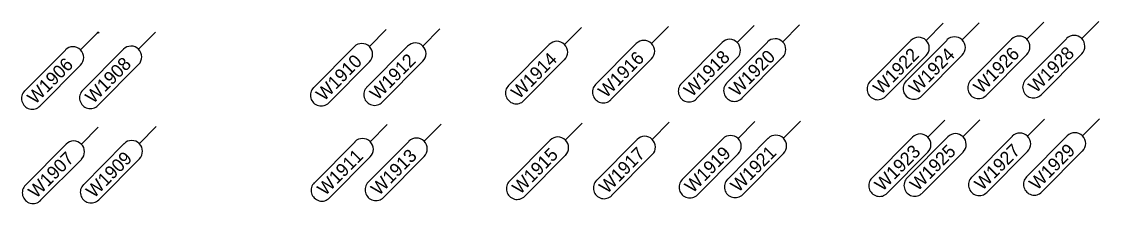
# Model space of a CAD drawing. Extents: x 12479652 to 12487250, y 9842710 to 9846560.
# Drawn here: x 12483341.6 to 12483444.7, y 9842833.3 to 9842850.7 of the extents above; entities that cross this region are included whole.
import ezdxf

# ---------------------------------------------------------------- set-up
doc = ezdxf.new("R2010")
doc.units = 0
doc.layers.add('_CIVIL_CONSTRUCTION', color=7, linetype='Continuous')
doc.layers.add('TextAlignmentLrg', color=7, linetype='Continuous')

msp = doc.modelspace()

# ---------------------------------------------------------------- linework, layer by layer
at = {"layer": '_CIVIL_CONSTRUCTION'}
for p, q in [((12483381.61, 9842849.99), (12483379.99, 9842848.36)), ((12483395.17, 9842850.14), (12483393.54, 9842848.51)), ((12483403.48, 9842850.23), (12483401.86, 9842848.6)), ((12483411.68, 9842850.33), (12483410.06, 9842848.69)), ((12483416.02, 9842850.37), (12483414.4, 9842848.74)), ((12483429.75, 9842850.53), (12483428.13, 9842848.9)), ((12483433.2, 9842850.57), (12483431.58, 9842848.94)), ((12483439.37, 9842850.64), (12483437.75, 9842849.01)), ((12483444.63, 9842850.7), (12483443.01, 9842849.07)), ((12483348.87, 9842849.62), (12483347.25, 9842847.99)), ((12483354.42, 9842849.68), (12483352.8, 9842848.05)), ((12483376.5, 9842849.93), (12483374.88, 9842848.3)), ((12483432.41, 9842845.09), (12483436.3, 9842849)), ((12483437.66, 9842845.15), (12483441.55, 9842849.06)), ((12483341.91, 9842844.07), (12483345.8, 9842847.98)), ((12483347.46, 9842844.13), (12483351.35, 9842848.05)), ((12483369.54, 9842844.38), (12483373.43, 9842848.29)), ((12483374.65, 9842844.44), (12483378.54, 9842848.35)), ((12483388.2, 9842844.59), (12483392.09, 9842848.5)), ((12483396.52, 9842844.69), (12483400.41, 9842848.6)), ((12483404.72, 9842844.78), (12483408.61, 9842848.69)), ((12483409.06, 9842844.83), (12483412.95, 9842848.74)), ((12483422.79, 9842844.98), (12483426.68, 9842848.89)), ((12483426.24, 9842845.02), (12483430.13, 9842848.93)), ((12483379.99, 9842846.91), (12483376.1, 9842842.99)), ((12483393.55, 9842847.06), (12483389.66, 9842843.15)), ((12483401.87, 9842847.15), (12483397.98, 9842843.24)), ((12483410.07, 9842847.24), (12483406.18, 9842843.33)), ((12483414.4, 9842847.29), (12483410.51, 9842843.38)), ((12483428.13, 9842847.45), (12483424.24, 9842843.53)), ((12483431.58, 9842847.49), (12483427.69, 9842843.57)), ((12483437.76, 9842847.56), (12483433.87, 9842843.64)), ((12483443.01, 9842847.61), (12483439.12, 9842843.7)), ((12483347.26, 9842846.54), (12483343.37, 9842842.62)), ((12483352.81, 9842846.6), (12483348.92, 9842842.69)), ((12483374.89, 9842846.85), (12483371, 9842842.93)), ((12483376.58, 9842840.85), (12483374.96, 9842839.21)), ((12483381.73, 9842840.89), (12483380.11, 9842839.26)), ((12483395.24, 9842841), (12483393.62, 9842839.37)), ((12483403.56, 9842841.07), (12483401.94, 9842839.44)), ((12483411.76, 9842841.14), (12483410.14, 9842839.51)), ((12483416.1, 9842841.17), (12483414.48, 9842839.54)), ((12483429.91, 9842841.29), (12483428.29, 9842839.66)), ((12483433.28, 9842841.32), (12483431.65, 9842839.68)), ((12483439.45, 9842841.37), (12483437.83, 9842839.74)), ((12483444.7, 9842841.41), (12483443.08, 9842839.78)), ((12483348.95, 9842840.62), (12483347.33, 9842838.98)), ((12483354.5, 9842840.66), (12483352.88, 9842839.03)), ((12483426.31, 9842835.77), (12483430.2, 9842839.68)), ((12483432.49, 9842835.82), (12483436.38, 9842839.73)), ((12483437.74, 9842835.86), (12483441.63, 9842839.78)), ((12483341.99, 9842835.07), (12483345.88, 9842838.98)), ((12483347.54, 9842835.11), (12483351.43, 9842839.03)), ((12483369.62, 9842835.3), (12483373.51, 9842839.21)), ((12483374.77, 9842835.34), (12483378.66, 9842839.25)), ((12483388.28, 9842835.45), (12483392.17, 9842839.36)), ((12483396.6, 9842835.52), (12483400.49, 9842839.43)), ((12483404.8, 9842835.59), (12483408.69, 9842839.5)), ((12483409.13, 9842835.62), (12483413.02, 9842839.54)), ((12483422.95, 9842835.74), (12483426.84, 9842839.65)), ((12483374.96, 9842837.76), (12483371.07, 9842833.85)), ((12483380.12, 9842837.81), (12483376.23, 9842833.89)), ((12483393.63, 9842837.92), (12483389.74, 9842834.01)), ((12483401.94, 9842837.99), (12483398.05, 9842834.07)), ((12483410.14, 9842838.06), (12483406.25, 9842834.14)), ((12483414.48, 9842838.09), (12483410.59, 9842834.18)), ((12483428.29, 9842838.21), (12483424.4, 9842834.29)), ((12483431.66, 9842838.23), (12483427.77, 9842834.32)), ((12483437.83, 9842838.29), (12483433.94, 9842834.37)), ((12483443.09, 9842838.33), (12483439.2, 9842834.42)), ((12483347.33, 9842837.53), (12483343.44, 9842833.62)), ((12483352.88, 9842837.58), (12483348.99, 9842833.67))]:
    msp.add_line(p, q, dxfattribs=at)
for centre, start, end in [((12483409.34, 9842847.97), 315.1702, 135.1702), ((12483413.68, 9842848.02), 315.1702, 135.1702), ((12483427.4, 9842848.17), 315.1702, 135.1702), ((12483430.85, 9842848.21), 315.1702, 135.1702), ((12483437.03, 9842848.28), 315.1702, 135.1702), ((12483442.28, 9842848.34), 315.1702, 135.1702), ((12483346.53, 9842847.26), 315.1702, 135.1702), ((12483352.08, 9842847.32), 315.1702, 135.1702), ((12483374.16, 9842847.57), 315.1702, 135.1702), ((12483379.27, 9842847.63), 315.1702, 135.1702), ((12483392.82, 9842847.78), 315.1702, 135.1702), ((12483401.14, 9842847.87), 315.1702, 135.1702), ((12483409.79, 9842844.1), 135.1702, 315.1702), ((12483423.51, 9842844.26), 135.1702, 315.1702), ((12483426.96, 9842844.3), 135.1702, 315.1702), ((12483433.14, 9842844.37), 135.1702, 315.1702), ((12483438.39, 9842844.43), 135.1702, 315.1702), ((12483342.64, 9842843.35), 135.1702, 315.1702), ((12483348.19, 9842843.41), 135.1702, 315.1702), ((12483370.27, 9842843.66), 135.1702, 315.1702), ((12483375.38, 9842843.72), 135.1702, 315.1702), ((12483388.93, 9842843.87), 135.1702, 315.1702), ((12483397.25, 9842843.96), 135.1702, 315.1702), ((12483405.45, 9842844.05), 135.1702, 315.1702), ((12483401.21, 9842838.71), 315.1702, 135.1702), ((12483409.42, 9842838.78), 315.1702, 135.1702), ((12483413.75, 9842838.81), 315.1702, 135.1702), ((12483427.56, 9842838.93), 315.1702, 135.1702), ((12483430.93, 9842838.96), 315.1702, 135.1702), ((12483437.1, 9842839.01), 315.1702, 135.1702), ((12483442.36, 9842839.05), 315.1702, 135.1702), ((12483346.6, 9842838.26), 315.1702, 135.1702), ((12483352.15, 9842838.3), 315.1702, 135.1702), ((12483374.23, 9842838.49), 315.1702, 135.1702), ((12483379.39, 9842838.53), 315.1702, 135.1702), ((12483392.9, 9842838.64), 315.1702, 135.1702), ((12483405.53, 9842834.87), 135.1702, 315.1702), ((12483409.86, 9842834.9), 135.1702, 315.1702), ((12483423.67, 9842835.02), 135.1702, 315.1702), ((12483427.04, 9842835.04), 135.1702, 315.1702), ((12483433.21, 9842835.1), 135.1702, 315.1702), ((12483438.47, 9842835.14), 135.1702, 315.1702), ((12483342.71, 9842834.34), 135.1702, 315.1702), ((12483348.26, 9842834.39), 135.1702, 315.1702), ((12483370.34, 9842834.57), 135.1702, 315.1702), ((12483375.5, 9842834.62), 135.1702, 315.1702), ((12483389.01, 9842834.73), 135.1702, 315.1702), ((12483397.33, 9842834.8), 135.1702, 315.1702)]:
    msp.add_arc(centre, 1.03, start, end, dxfattribs=at)
at = {"layer": 'TextAlignmentLrg'}
msp.add_circle((12483348.94, 9842849.64), 0.05, dxfattribs=at)

# ---------------------------------------------------------------- texts
at = {"layer": '_CIVIL_CONSTRUCTION'}
for s, p in [('W1920', (12483410.06, 9842843.47)), ('W1922', (12483423.81, 9842843.65)), ('W1924', (12483427.23, 9842843.66)), ('W1926', (12483433.41, 9842843.74)), ('W1928', (12483438.66, 9842843.8)), ('W1906', (12483342.91, 9842842.72)), ('W1908', (12483348.46, 9842842.78)), ('W1910', (12483370.54, 9842843.03)), ('W1912', (12483375.67, 9842843.11)), ('W1914', (12483389.2, 9842843.23)), ('W1916', (12483397.52, 9842843.33)), ('W1918', (12483405.72, 9842843.43)), ('W1915', (12483389.29, 9842834.11)), ('W1917', (12483397.61, 9842834.18)), ('W1919', (12483405.8, 9842834.24)), ('W1921', (12483410.17, 9842834.31)), ('W1923', (12483423.95, 9842834.4)), ('W1925', (12483427.33, 9842834.43)), ('W1927', (12483433.5, 9842834.48)), ('W1929', (12483438.74, 9842834.51)), ('W1907', (12483343, 9842833.73)), ('W1909', (12483348.54, 9842833.76)), ('W1911', (12483370.65, 9842833.98)), ('W1913', (12483375.78, 9842834))]:
    msp.add_text(s, height=1.25, rotation=45.1702, dxfattribs=at).set_placement(p)

doc.saveas('drawing.dxf')
